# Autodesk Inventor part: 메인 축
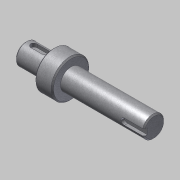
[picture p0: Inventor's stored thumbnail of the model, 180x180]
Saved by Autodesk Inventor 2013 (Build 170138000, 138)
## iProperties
Created: 2016-04
Part Number: 메인 축
Document SubType Name: Modeling
Designer: mdu
Density: 7.86 g/cm^3
Mass: 230.24 g
Surface Area: 74.3518 cm^2
Volume: 29.2926 cm^3
Material: 강철, 연강
Author: mdu
Revision Number: 1
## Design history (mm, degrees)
sketch "스케치1"
  geometry: L1 (10.497, -57.5)-(112.497, -57.5); L2 (10.497, -66)-(32.497, -66); L3 (32.497, -72.5)-(46.5, -72.5); L4 (46.5, -66)-(112.497, -66); L5 (112.497, -66)-(112.497, -57.5); L6 (10.497, -66)-(10.497, -57.5); L7 (46.5, -69.749)-(46.5, -45.251) reference; L8 (46.5, -72.5)-(46.5, -66); L9 (32.497, -72.5)-(32.497, -66); L10 (32.497, -35)-(32.497, -80) reference; 3 further points
  constraints: 16 end point, 3 point on line, 2 parallel, 2 perpendicular, 1 collinear, 1 horizontal, 1 midpoint
  dimensions: "d0" = 17 diameter of L4 L1; "d1" = 30 diameter of L3 L1; "d2" = 22 distance of L2.start L2.end; "d3" = 65.99692 distance of L4.start L4.end (derived); "d5" = 17 diameter of L2 L1; "d19" = 80 distance between parallel lines of L5 L9
revolve "회전1" sketch "스케치1" stored, may be unused: angle "d4" = 90 deg
chamfer "모따기1" distance "d6" = 1; stored, may be unused: second distance "d7" = 2, angle "d8" = 45 deg
node "작업 평면1"
sketch "스케치2"
  geometry: L1 (-11, -7.5)-(-11, 7.5) reference; L2 (-4.5, 2.5)-(4.5, 2.5); L3 (4.5, -2.5)-(-4.5, -2.5); A1 r 2.5 centre (4.5, 0) between (4.5, -2.5) and (4.5, 2.5); A2 r 2.5 centre (-4.5, 0) between (-4.5, 2.5) and (-4.5, -2.5); 2 further points
  constraints: 4 end point, 4 point on circle, 4 tangent, 2 centre point, 1 horizontal alignment, 1 midpoint, 1 parallel, 1 perpendicular
  dimensions: "d9" = 5 distance between parallel lines of L3 L2; "d10" = 14 dimension on A1 A2; "d11" = 4 distance edge to line of A2 L1
extrude "돌출1" cut sketch "스케치2" distance "d12" = 3; taper "d13" = 0 deg
node "작업 평면2"
sketch "스케치3"
  geometry: L1 (32.998, 7.5)-(32.998, -7.5) reference; L2 (32.998, 2.5)-(17.498, 2.5); L3 (17.498, -2.5)-(32.998, -2.5); A1 r 2.5 centre (17.498, 0) between (17.498, 2.5) and (17.498, -2.5); 2 further points
  constraints: 4 end point, 2 perpendicular, 2 point on circle, 2 point on line, 2 tangent, 1 centre point, 1 horizontal alignment, 1 midpoint
  dimensions: "d14" = 5 distance between parallel lines of L3 L2; "d15" = 18 dimension on A1 L1
extrude "돌출2" cut sketch "스케치3" distance "d16" = 3; taper "d17" = 0 deg
node "솔리드1"
node "참조4"
node "참조5"
